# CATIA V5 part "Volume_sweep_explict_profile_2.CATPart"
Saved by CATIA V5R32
Part number: Part1
Bounding box of the stored display mesh (mm): x -0.366 to 107.273, y -258.378 to 1.302, z -19.914 to 111.945
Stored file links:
  D:\PROJECTS\Project 2022\CATIA V5 6R 2022\Resources\Part Files\c17_catia_v6_6r2022_prt\Volume_sweep_explict_profile_2.CATPart
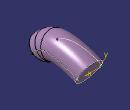
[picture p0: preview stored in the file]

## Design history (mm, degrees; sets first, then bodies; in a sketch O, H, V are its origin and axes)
Set1
  Sketch1 on yz-plane, origin (0, 0, 0), H (0, 1, 0), V (0, 0, 1)
    spline S1 through (-23.0016, 27.4581) (-75.0426, 47.0094) (-171.9366, 48.7346) (-214.202, 27.4581)
  Plane1: type Offset, RefPlane yz-plane, Offset 107
  Sketch2 on Plane1, origin (107, 0, 0), H (0, 1, 0), V (0, 0, 1)
    spline S1 through (-23.0016, 27.4581) (-104.0993, 55.4238) (-183.694, 56.9883) (-214.202, 27.4581)
    reference projected point E1 (-214.202, 27.4581) from vertex of Sketch1
    reference projected point E2 (-23.0016, 27.4581) from vertex of Sketch1
    point P1 (-214.202, 27.4581)
    point P2 (-23.0016, 27.4581)
    coincidence: P1 E1, P2 E2
  Plane2: type Normal, Curve Sketch1, RefPoint vertex of Sketch1, Ratio 0
  Sketch3 on Plane2, origin (0, -29.3756, 14.8457), H (1, 0, 0), V (0, 0.451, 0.8925)
    circle A1 centre (53.5, 14.5287) radius 53.5015
    reference projected point E1 (107, 14.1316) from Sketch2.P2
    reference projected point E2 (0, 14.1316) from vertex of Sketch1
    coincidence: A1 E1, A1 E2
  Sketch4 on Plane2, origin (0, -29.3756, 14.8457), H (1, 0, 0), V (0, 0.451, 0.8925)
    point P1 (107, 14.1316)
    reference projected point E1 (107, 14.1316) from Sketch2.P2
    coincidence: P1 E1
  Sketch5 on Plane2, origin (0, -29.3756, 14.8457), H (1, 0, 0), V (0, 0.451, 0.8925)
    point P1 (0, 14.1316)
    reference projected point E1 (0, 14.1316) from vertex of Sketch1
    coincidence: P1 E1
  Sweep1: type Unspec, Profile Sketch3, Guide (Sketch2; Sketch1), FittingPoints (Sketch4; Sketch5)
Body1 (main body)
